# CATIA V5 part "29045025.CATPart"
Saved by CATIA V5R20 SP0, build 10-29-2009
Part number: 29045025
Definition: NONE
Nomenclature: 29045025
Source: Unknown
Description: 29045025
Bounding box of the stored display mesh (mm): x -12.5 to 44.548, y -36.5 to 71.048, z -26.5 to 26.5
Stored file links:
  C:\Users\Utente\Desktop\IO LAVORO\3D X SITO CF\X SITO\PLASTICA\RF1\29045025.CATPart
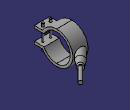
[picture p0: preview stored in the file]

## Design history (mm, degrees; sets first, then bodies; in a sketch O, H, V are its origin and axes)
Body1 "29045025" (main body)
  Solid1: solid without history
